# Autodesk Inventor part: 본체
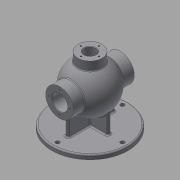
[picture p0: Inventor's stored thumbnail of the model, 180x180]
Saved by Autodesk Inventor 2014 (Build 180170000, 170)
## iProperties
Created: 2020-08
Part Number: 본체
Material: Generic
Document SubType Name: Modeling
Designer: kh
Density: 1 g/cm^3
Appearance: Default
Author: kh
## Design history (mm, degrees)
sketch "Sketch1"
  geometry: L1 (0, 53)-(0, -53); A1 r 53 centre (0, 0) between (0, -53) and (0, 53); A2 r 43 centre (0, 0) between (0, -43) and (0, 43); 1 further point
  constraints: 4 point on circle, 2 centre point, 2 coincident, 2 end point, 2 point on line, 1 midpoint, 1 vertical
  dimensions: "d1" = 53 radius of A1; "d4" = 43 radius of A2
revolve "Revolution1" stored, may be unused: angle "d2" = 90 deg
revolve "Revolution2" stored, may be unused: angle "d5" = 90 deg
workplane "Work Plane1"
sketch "Sketch2"
  geometry: C1 r 31 at (0, 0); 1 further point
  constraints: 1 centre point, 1 coincident
  dimensions: "d7" = 62 diameter of C1
extrude "Extrusion1" join sketch "Sketch2" stored distance "d8" = 10; taper "d9" = 0 deg
sketch "Sketch3"
  geometry: C1 r 17.5 at (0, 0); 1 further point
  constraints: 1 centre point, 1 coincident
  dimensions: "d10" = 35 diameter of C1
extrude "Extrusion2" cut sketch "Sketch3" stored distance "d11" = 10; taper "d12" = 0 deg
mirror "Mirror1"
workplane "Work Plane2"
sketch "Sketch4"
  geometry: C1 r 85 at (0, 0); 1 further point
  constraints: 1 centre point, 1 coincident
  dimensions: "d14" = 170 diameter of C1
extrude "Extrusion3" join sketch "Sketch4" distance "d15" = 10; taper "d16" = 0 deg
workplane "Work Plane4"
  workplane "Work Plane3"
sketch "Sketch5"
  geometry: C1 r 18.5 at (0, 0); 1 further point
  constraints: 1 centre point, 1 coincident
  dimensions: "d19" = 37 diameter of C1
extrude "Extrusion4" cut sketch "Sketch5" distance "d20" = 1.75; taper "d21" = 0 deg
workplane "Work Plane5"
sketch "Sketch6"
  geometry: C1 r 27 at (0, 0); 1 further point
  constraints: 1 centre point, 1 coincident
  dimensions: "d23" = 54 diameter of C1
extrude "Extrusion5" join sketch "Sketch6" stored distance "d24" = 1.75; taper "d25" = 0 deg
sketch "Sketch7"
  geometry: C1 r 13 at (0, 0); 1 further point
  constraints: 1 centre point, 1 coincident
  dimensions: "d26" = 26 diameter of C1
extrude "Extrusion6" cut sketch "Sketch7" stored distance "d27" = 1.75; taper "d28" = 0 deg
sketch "Sketch8"
  geometry: A1 r 20 centre (0, 0) between (0, 20) and (0, -20); 3 further points
  constraints: 4 point on circle, 2 horizontal alignment, 2 vertical alignment, 1 centre point, 1 coincident
  dimensions: "d29" = 40 diameter of A1
hole "Hole1" sketch "Sketch8" at (0, 20), (0, -20), (-20, 0), (20, 0) diameter "d30" = 3.242; stored, may be unused: countersink angle "d34" = 90 deg, drill point angle "d36" = 118 deg; dims "d31" = 12, "d32" = 4, "d33" = 2, "d35" = 15
sketch "Sketch9"
  geometry: A1 r 24 centre (0, 0) between (0, 24) and (24, 0); 3 further points
  constraints: 4 point on circle, 2 horizontal alignment, 2 vertical alignment, 1 centre point, 1 coincident
  dimensions: "d37" = 48 diameter of A1
hole "Hole2" sketch "Sketch9" at (0, 24), (24, 0), (-24, 0), (0, -24) diameter "d38" = 3.242; stored, may be unused: countersink angle "d42" = 90 deg, drill point angle "d44" = 118 deg; dims "d39" = 12, "d40" = 4, "d41" = 2, "d43" = 15
mirror "Mirror2"
sketch "Sketch10"
  geometry: L1 (-52, -4)-(52, -4); L2 (52, -4)-(52, 4); L3 (52, 4)-(-52, 4); L4 (-52, 4)-(-52, -4); L5 (-52, -4)-(52, 4); L6 (52, -4)-(-52, 4); L7 (-4, -43)-(4, -43); L8 (4, -43)-(4, 43); L9 (4, 43)-(-4, 43); L10 (-4, 43)-(-4, -43); L11 (-4, -43)-(4, 43); L12 (4, -43)-(-4, 43); 1 further point
  constraints: 24 end point, 4 midpoint, 4 parallel, 2 horizontal, 2 perpendicular
  dimensions: "d45" = 86 distance of L7.end L8.end; "d46" = 104 distance of L1.start L1.end; "d47" = 8 distance of L1.end L2.end; "d48" = 8 distance of L7.start L7.end
extrude "Extrusion7" join sketch "Sketch10" stored distance "d49" = 1.75; taper "d50" = 0 deg
fillet "Fillet1" dims "d51" = 3
fillet "Fillet2" dims "d52" = 3
fillet "Fillet3" dims "d53" = 3
chamfer "Chamfer1" distance "d54" = 1; stored, may be unused: second distance "d55" = 2, angle "d56" = 45 deg
sketch "Sketch11"
  geometry: C1 r 4.5 at (72.5, 0); C2 r 4.5 at (0, -72.5); C3 r 4.5 at (-72.5, 0); C4 r 4.5 at (0, 72.5); A1 r 72.5 centre (0, 0) between (72.5, 0) and (0, -72.5); 1 further point
  constraints: 5 centre point, 4 point on circle, 2 horizontal alignment, 2 vertical alignment, 1 coincident
  dimensions: "d57" = 145 diameter of A1; "d58" = 9 diameter of C1; "d59" = 9 diameter of C2; "d60" = 9 diameter of C3; "d61" = 9 diameter of C4
extrude "Extrusion8" cut sketch "Sketch11" stored distance "d62" = 0; taper "d63" = 0 deg
fillet "Fillet4" dims "d64" = 3
body "Solid1"
other parameters: "d6" = 68, "d13" = -85, "d17" = -68, "d18" = 16
